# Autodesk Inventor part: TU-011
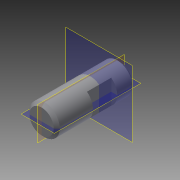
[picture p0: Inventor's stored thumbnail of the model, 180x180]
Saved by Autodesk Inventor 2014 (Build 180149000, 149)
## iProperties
Shininess: 64.0
Angle Display Precision: 2
Document Length Units: 11269
Document Angle Units: 11279
Document Time Units: 11290
Document Mass Units: 11283
Document Length Units Precision: 3
Document Angle Units Precision: 2
Compacted: True
Created: 2002-07
Part Number: TU-011
Document SubType Name: Modeling
Designer: PN
Description: Lock Pin
Density: 1 g/cm^3
Mass: 1.92325 g
Surface Area: 9.46666 cm^2
Volume: 1.92325 cm^3
Material: Generic
Appearance: Default
Density: 0.0
Volumn: 0.0
Area: 0.0
PropertySet Name: Model Information
Control State: 0
Master: False
Checked Out: False
Author: PN
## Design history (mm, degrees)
sketch "Sketch1"
  geometry: C1 r 5 at (0, 0); 1 further point
  constraints: 1 centre point, 1 coincident
  dimensions: "d0" = 10 diameter of C1
extrude "Extrusion1" new body sketch "Sketch1" stored distance "d1" = 26; taper "d2" = 0 deg
chamfer "Chamfer1" distance "d3" = 1; stored, may be unused: second distance "d4" = 1, angle "d10" = 45 deg
sketch "Sketch2"
  geometry: L1 (-5, -12)-(-5, 12) reference; L2 (-5, 7)-(-3, 7); L3 (-3, 7)-(-3, -1); L4 (-3, -1)-(-5, -1); L5 (-5, -1)-(-5, 7); L6 (-4, 13)-(4, 13) reference
  constraints: 8 end point, 2 parallel, 1 horizontal, 1 perpendicular, 1 point on line
  dimensions: "d5" = 2 distance of L2.start L2.end; "d6" = 8 distance of L2.end L3.end; "d7" = 6 distance between parallel lines of L2 L6
extrude "Extrusion2" cut sketch "Sketch2" stored distance "d8" = 26; taper "d9" = 0 deg
workplane "Work Plane1"
body "Solid1"
